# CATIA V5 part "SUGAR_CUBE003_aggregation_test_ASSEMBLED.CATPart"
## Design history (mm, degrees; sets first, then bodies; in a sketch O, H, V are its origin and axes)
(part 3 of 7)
Body19 "sugar_cube003_Ac004"
  Line128: type PtDir, RefPoint Point8, Direction edge [XY plane of AxisSystem1 | ZX plane of AxisSystem1], Start 0, End 3048 {= Body19.X1}
  Line129: type PtDir, RefPoint Point8, Direction edge [XY plane of AxisSystem1 | ZX plane of AxisSystem1], Start 0, End 5486.4 {= Body19.X2}
  Line130: type PtDir, RefPoint Point8, Direction edge [YZ plane of AxisSystem1 | XY plane of AxisSystem1], Start 0, End 3352.8 {= Body19.Y1}
  Line131: type PtDir, RefPoint Point8, Direction edge [YZ plane of AxisSystem1 | XY plane of AxisSystem1], Start 0, End 4572 {= Body19.Y2}
  Line132: type PtDir, RefPoint Point8, Direction edge [ZX plane of AxisSystem1 | YZ plane of AxisSystem1], Start 0, End 4876.8 {= Body19.Z1}
  Line133: type PtDir, RefPoint Point8, Direction edge [ZX plane of AxisSystem1 | YZ plane of AxisSystem1], Start 0, End 4572 {= Body19.Z2}
  Plane232: type Normal, Curve Line128, RefPoint vertex of Line128
  Plane233: type Normal, Curve Line129, RefPoint vertex of Line129
  Plane234: type Normal, Curve Line130, RefPoint vertex of Line130
  Plane235: type Normal, Curve Line131, RefPoint vertex of Line131
  Plane236: type Normal, Curve Line132, RefPoint vertex of Line132
  Plane237: type Normal, Curve Line133, RefPoint vertex of Line133
  Plane238: type 3Points, Element1 Point8, Element2 vertex of Line130, Element3 vertex of Line128
  Intersect341: ToIntersect1 Plane234, ToIntersect2 Plane233
  Intersect342: ToIntersect1 Plane232, ToIntersect2 Plane234
  Intersect343: ToIntersect1 Plane232, ToIntersect2 Plane235
  Intersect344: ToIntersect1 Plane235, ToIntersect2 Plane233
  MultiSel18
  LineCorner18: Elements ({intersect ToIntersect1 Plane238, ToIntersect2 Intersect343}; {intersect ToIntersect1 Plane238, ToIntersect2 Intersect344}; {intersect ToIntersect1 Plane238, ToIntersect2 Intersect341}; {intersect ToIntersect1 Plane238, ToIntersect2 Intersect342})
  Pad70: profile LineCorner18, up to Plane236, opposite side up to Plane237
  Plane239: type Offset, RefPlane Plane235, Offset 609.6 {= thickness}
  Plane240: type Offset, RefPlane Plane234, Offset 609.6 {= thickness}, reversed
  Plane241: type Offset, RefPlane Plane232, Offset 609.6 {= thickness}, reversed
  Plane242: type Offset, RefPlane Plane233, Offset 609.6 {= thickness}
  Plane243: type Offset, RefPlane Plane237, Offset 609.6 {= thickness}
  Plane244: type Offset, RefPlane Plane236, Offset 609.6 {= thickness}, reversed
  Intersect345: ToIntersect1 Plane239, ToIntersect2 Plane232
  Intersect346: ToIntersect1 Plane240, ToIntersect2 Plane232
  Intersect347: ToIntersect1 Plane243, ToIntersect2 Plane232
  Intersect348: ToIntersect1 Plane244, ToIntersect2 Plane232
  Trim205: Trimmed (Intersect345; Intersect348)
  Trim206: Trimmed (Trim205; Intersect346)
  Trim207: Trimmed (Trim206; Intersect347)
  Pocket74: profile Trim207, up to Plane242, deactivated
  Pad71: profile LineCorner18, up to Plane236, opposite side up to Plane237, deactivated
  Intersect349: ToIntersect1 Plane240, ToIntersect2 Plane233
  Intersect350: ToIntersect1 Plane233, ToIntersect2 Plane239
  Intersect351: ToIntersect1 Plane243, ToIntersect2 Plane233
  Intersect352: ToIntersect1 Plane244, ToIntersect2 Plane233
  Trim208: Trimmed (Intersect352; Intersect349)
  Trim209: Trimmed (Trim208; Intersect351)
  Trim210: Trimmed (Trim209; Intersect350)
  Pocket75: profile Trim210, up to Plane241, deactivated
  Intersect353: ToIntersect1 Plane242, ToIntersect2 Plane235
  Intersect354: ToIntersect1 Plane243, ToIntersect2 Plane235
  Intersect355: ToIntersect1 Plane235, ToIntersect2 Plane241
  Intersect356: ToIntersect1 Plane244, ToIntersect2 Plane235
  Trim211: Trimmed (Intersect353; Intersect356)
  Trim212: Trimmed (Trim211; Intersect355)
  Trim213: Trimmed (Trim212; Intersect354)
  Pad72: profile LineCorner18, up to Plane236, opposite side up to Plane237, deactivated
  Pocket76: profile Trim213, up to Plane240, deactivated
  Intersect357: ToIntersect1 Plane241, ToIntersect2 Plane234
  Intersect358: ToIntersect1 Plane243, ToIntersect2 Plane234
  Intersect359: ToIntersect1 Plane242, ToIntersect2 Plane234
  Intersect360: ToIntersect1 Plane244, ToIntersect2 Plane234
  Trim214: Trimmed (Intersect357; Intersect360)
  Trim215: Trimmed (Trim214; Intersect359)
  Trim216: Trimmed (Trim215; Intersect358)
  Pad73: profile LineCorner18, up to Plane236, opposite side up to Plane237
  Pocket77: profile Trim216, up to Plane239
Body20 "sugar_cube003_Ad004"
  Line134: type PtDir, RefPoint Point4, Direction edge [XY plane of AxisSystem1 | ZX plane of AxisSystem1], Start 0, End 3048 {= Body20.X1}
  Line135: type PtDir, RefPoint Point4, Direction edge [XY plane of AxisSystem1 | ZX plane of AxisSystem1], Start 0, End 4876.8 {= Body20.X2}
  Line136: type PtDir, RefPoint Point4, Direction edge [YZ plane of AxisSystem1 | XY plane of AxisSystem1], Start 0, End 5791.2 {= Body20.Y1}
  Line137: type PtDir, RefPoint Point4, Direction edge [YZ plane of AxisSystem1 | XY plane of AxisSystem1], Start 0, End 3048 {= Body20.Y2}
  Line138: type PtDir, RefPoint Point4, Direction edge [ZX plane of AxisSystem1 | YZ plane of AxisSystem1], Start 0, End 4876.8 {= Body20.Z1}
  Line139: type PtDir, RefPoint Point4, Direction edge [ZX plane of AxisSystem1 | YZ plane of AxisSystem1], Start 0, End 3962.4 {= Body20.Z2}
  Plane245: type Normal, Curve Line134, RefPoint vertex of Line134
  Plane246: type Normal, Curve Line135, RefPoint vertex of Line135
  Plane247: type Normal, Curve Line136, RefPoint vertex of Line136
  Plane248: type Normal, Curve Line137, RefPoint vertex of Line137
  Plane249: type Normal, Curve Line138, RefPoint vertex of Line138
  Plane250: type Normal, Curve Line139, RefPoint vertex of Line139
  Plane251: type 3Points, Element1 Point4, Element2 vertex of Line136, Element3 vertex of Line134
  Intersect361: ToIntersect1 Plane247, ToIntersect2 Plane246
  Intersect362: ToIntersect1 Plane245, ToIntersect2 Plane247
  Intersect363: ToIntersect1 Plane245, ToIntersect2 Plane248
  Intersect364: ToIntersect1 Plane248, ToIntersect2 Plane246
  MultiSel19
  LineCorner19: Elements ({intersect ToIntersect1 Plane251, ToIntersect2 Intersect363}; {intersect ToIntersect1 Plane251, ToIntersect2 Intersect364}; {intersect ToIntersect1 Plane251, ToIntersect2 Intersect361}; {intersect ToIntersect1 Plane251, ToIntersect2 Intersect362})
  Pad74: profile LineCorner19, up to Plane249, opposite side up to Plane250, deactivated
  Plane252: type Offset, RefPlane Plane248, Offset 609.6 {= thickness}
  Plane253: type Offset, RefPlane Plane247, Offset 609.6 {= thickness}, reversed
  Plane254: type Offset, RefPlane Plane245, Offset 609.6 {= thickness}, reversed
  Plane255: type Offset, RefPlane Plane246, Offset 609.6 {= thickness}
  Plane256: type Offset, RefPlane Plane250, Offset 609.6 {= thickness}
  Plane257: type Offset, RefPlane Plane249, Offset 609.6 {= thickness}, reversed
  Intersect365: ToIntersect1 Plane252, ToIntersect2 Plane245
  Intersect366: ToIntersect1 Plane253, ToIntersect2 Plane245
  Intersect367: ToIntersect1 Plane256, ToIntersect2 Plane245
  Intersect368: ToIntersect1 Plane257, ToIntersect2 Plane245
  Trim217: Trimmed (Intersect365; Intersect368)
  Trim218: Trimmed (Trim217; Intersect366)
  Trim219: Trimmed (Trim218; Intersect367)
  Pocket78: profile Trim219, up to Plane255, deactivated
  Pad75: profile LineCorner19, up to Plane249, opposite side up to Plane250, deactivated
  Intersect369: ToIntersect1 Plane253, ToIntersect2 Plane246
  Intersect370: ToIntersect1 Plane246, ToIntersect2 Plane252
  Intersect371: ToIntersect1 Plane256, ToIntersect2 Plane246
  Intersect372: ToIntersect1 Plane257, ToIntersect2 Plane246
  Trim220: Trimmed (Intersect372; Intersect369)
  Trim221: Trimmed (Trim220; Intersect371)
  Trim222: Trimmed (Trim221; Intersect370)
  Pocket79: profile Trim222, up to Plane254, deactivated
  Intersect373: ToIntersect1 Plane255, ToIntersect2 Plane248
  Intersect374: ToIntersect1 Plane256, ToIntersect2 Plane248
  Intersect375: ToIntersect1 Plane248, ToIntersect2 Plane254
  Intersect376: ToIntersect1 Plane257, ToIntersect2 Plane248
  Trim223: Trimmed (Intersect373; Intersect376)
  Trim224: Trimmed (Trim223; Intersect375)
  Trim225: Trimmed (Trim224; Intersect374)
  Pad76: profile LineCorner19, up to Plane249, opposite side up to Plane250
  Pocket80: profile Trim225, up to Plane253
  Intersect377: ToIntersect1 Plane254, ToIntersect2 Plane247
  Intersect378: ToIntersect1 Plane256, ToIntersect2 Plane247
  Intersect379: ToIntersect1 Plane255, ToIntersect2 Plane247
  Intersect380: ToIntersect1 Plane257, ToIntersect2 Plane247
  Trim226: Trimmed (Intersect377; Intersect380)
  Trim227: Trimmed (Trim226; Intersect379)
  Trim228: Trimmed (Trim227; Intersect378)
  Pad77: profile LineCorner19, up to Plane249, opposite side up to Plane250, deactivated
  Pocket81: profile Trim228, up to Plane252, deactivated
Body21 "sugar_cube003_Ae004"
  Line140: type PtDir, RefPoint Point100, Direction edge [XY plane of AxisSystem1 | ZX plane of AxisSystem1], Start 0, End 6096 {= Body21.X1}
  Line141: type PtDir, RefPoint Point100, Direction edge [XY plane of AxisSystem1 | ZX plane of AxisSystem1], Start 0, End 3352.8 {= Body21.X2}
  Line142: type PtDir, RefPoint Point100, Direction edge [YZ plane of AxisSystem1 | XY plane of AxisSystem1], Start 0, End 3657.6 {= Body21.Y1}
  Line143: type PtDir, RefPoint Point100, Direction edge [YZ plane of AxisSystem1 | XY plane of AxisSystem1], Start 0, End 5181.6 {= Body21.Y2}
  Line144: type PtDir, RefPoint Point100, Direction edge [ZX plane of AxisSystem1 | YZ plane of AxisSystem1], Start 0, End 5791.2 {= Body21.Z1}
  Line145: type PtDir, RefPoint Point100, Direction edge [ZX plane of AxisSystem1 | YZ plane of AxisSystem1], Start 0, End 3962.4 {= Body21.Z2}
  Plane258: type Normal, Curve Line140, RefPoint vertex of Line140
  Plane259: type Normal, Curve Line141, RefPoint vertex of Line141
  Plane260: type Normal, Curve Line142, RefPoint vertex of Line142
  Plane261: type Normal, Curve Line143, RefPoint vertex of Line143
  Plane262: type Normal, Curve Line144, RefPoint vertex of Line144
  Plane263: type Normal, Curve Line145, RefPoint vertex of Line145
  Plane264: type 3Points, Element1 Point100, Element2 vertex of Line142, Element3 vertex of Line140
  Intersect381: ToIntersect1 Plane260, ToIntersect2 Plane259
  Intersect382: ToIntersect1 Plane258, ToIntersect2 Plane260
  Intersect383: ToIntersect1 Plane258, ToIntersect2 Plane261
  Intersect384: ToIntersect1 Plane261, ToIntersect2 Plane259
  MultiSel20
  LineCorner20: Elements ({intersect ToIntersect1 Plane264, ToIntersect2 Intersect383}; {intersect ToIntersect1 Plane264, ToIntersect2 Intersect384}; {intersect ToIntersect1 Plane264, ToIntersect2 Intersect381}; {intersect ToIntersect1 Plane264, ToIntersect2 Intersect382})
  Pad78: profile LineCorner20, up to Plane262, opposite side up to Plane263, deactivated
  Plane265: type Offset, RefPlane Plane261, Offset 609.6 {= thickness}
  Plane266: type Offset, RefPlane Plane260, Offset 609.6 {= thickness}, reversed
  Plane267: type Offset, RefPlane Plane258, Offset 609.6 {= thickness}, reversed
  Plane268: type Offset, RefPlane Plane259, Offset 609.6 {= thickness}
  Plane269: type Offset, RefPlane Plane263, Offset 609.6 {= thickness}
  Plane270: type Offset, RefPlane Plane262, Offset 609.6 {= thickness}, reversed
  Intersect385: ToIntersect1 Plane265, ToIntersect2 Plane258
  Intersect386: ToIntersect1 Plane266, ToIntersect2 Plane258
  Intersect387: ToIntersect1 Plane269, ToIntersect2 Plane258
  Intersect388: ToIntersect1 Plane270, ToIntersect2 Plane258
  Trim229: Trimmed (Intersect385; Intersect388)
  Trim230: Trimmed (Trim229; Intersect386)
  Trim231: Trimmed (Trim230; Intersect387)
  Pocket82: profile Trim231, up to Plane268, deactivated
  Pad79: profile LineCorner20, up to Plane262, opposite side up to Plane263, deactivated
  Intersect389: ToIntersect1 Plane266, ToIntersect2 Plane259
  Intersect390: ToIntersect1 Plane259, ToIntersect2 Plane265
  Intersect391: ToIntersect1 Plane269, ToIntersect2 Plane259
  Intersect392: ToIntersect1 Plane270, ToIntersect2 Plane259
  Trim232: Trimmed (Intersect392; Intersect389)
  Trim233: Trimmed (Trim232; Intersect391)
  Trim234: Trimmed (Trim233; Intersect390)
  Pocket83: profile Trim234, up to Plane267, deactivated
  Intersect393: ToIntersect1 Plane268, ToIntersect2 Plane261
  Intersect394: ToIntersect1 Plane269, ToIntersect2 Plane261
  Intersect395: ToIntersect1 Plane261, ToIntersect2 Plane267
  Intersect396: ToIntersect1 Plane270, ToIntersect2 Plane261
  Trim235: Trimmed (Intersect393; Intersect396)
  Trim236: Trimmed (Trim235; Intersect395)
  Trim237: Trimmed (Trim236; Intersect394)
  Pad80: profile LineCorner20, up to Plane262, opposite side up to Plane263, deactivated
  Pocket84: profile Trim237, up to Plane266, deactivated
  Intersect397: ToIntersect1 Plane267, ToIntersect2 Plane260
  Intersect398: ToIntersect1 Plane269, ToIntersect2 Plane260
  Intersect399: ToIntersect1 Plane268, ToIntersect2 Plane260
  Intersect400: ToIntersect1 Plane270, ToIntersect2 Plane260
  Trim238: Trimmed (Intersect397; Intersect400)
  Trim239: Trimmed (Trim238; Intersect399)
  Trim240: Trimmed (Trim239; Intersect398)
  Pad81: profile LineCorner20, up to Plane262, opposite side up to Plane263, deactivated
  Pocket85: profile Trim240, up to Plane265, deactivated
Body22 "sugar_cube003_Aa005"
  Line146: type PtDir, RefPoint Point17, Direction edge [XY plane of AxisSystem1 | ZX plane of AxisSystem1], Start 0, End 3352.8 {= Body22.X1}
  Line147: type PtDir, RefPoint Point17, Direction edge [XY plane of AxisSystem1 | ZX plane of AxisSystem1], Start 0, End 3048 {= Body22.X2}
  Line148: type PtDir, RefPoint Point17, Direction edge [YZ plane of AxisSystem1 | XY plane of AxisSystem1], Start 0, End 3962.4 {= Body22.Y1}
  Line149: type PtDir, RefPoint Point17, Direction edge [YZ plane of AxisSystem1 | XY plane of AxisSystem1], Start 0, End 4572 {= Body22.Y2}
  Line150: type PtDir, RefPoint Point17, Direction edge [ZX plane of AxisSystem1 | YZ plane of AxisSystem1], Start 0, End 3352.8 {= Body22.Z1}
  Line151: type PtDir, RefPoint Point17, Direction edge [ZX plane of AxisSystem1 | YZ plane of AxisSystem1], Start 0, End 5791.2 {= Body22.Z2}
  Plane271: type Normal, Curve Line146, RefPoint vertex of Line146
  Plane272: type Normal, Curve Line147, RefPoint vertex of Line147
  Plane273: type Normal, Curve Line148, RefPoint vertex of Line148
  Plane274: type Normal, Curve Line149, RefPoint vertex of Line149
  Plane275: type Normal, Curve Line150, RefPoint vertex of Line150
  Plane276: type Normal, Curve Line151, RefPoint vertex of Line151
  Plane277: type 3Points, Element1 Point17, Element2 vertex of Line148, Element3 vertex of Line146
  Intersect401: ToIntersect1 Plane273, ToIntersect2 Plane272
  Intersect402: ToIntersect1 Plane271, ToIntersect2 Plane273
  Intersect403: ToIntersect1 Plane271, ToIntersect2 Plane274
  Intersect404: ToIntersect1 Plane274, ToIntersect2 Plane272
  MultiSel21
  LineCorner21: Elements ({intersect ToIntersect1 Plane277, ToIntersect2 Intersect403}; {intersect ToIntersect1 Plane277, ToIntersect2 Intersect404}; {intersect ToIntersect1 Plane277, ToIntersect2 Intersect401}; {intersect ToIntersect1 Plane277, ToIntersect2 Intersect402})
  Pad82: profile LineCorner21, up to Plane275, opposite side up to Plane276, deactivated
  Plane278: type Offset, RefPlane Plane274, Offset 609.6 {= thickness}
  Plane279: type Offset, RefPlane Plane273, Offset 609.6 {= thickness}, reversed
  Plane280: type Offset, RefPlane Plane271, Offset 609.6 {= thickness}, reversed
  Plane281: type Offset, RefPlane Plane272, Offset 609.6 {= thickness}
  Plane282: type Offset, RefPlane Plane276, Offset 609.6 {= thickness}
  Plane283: type Offset, RefPlane Plane275, Offset 609.6 {= thickness}, reversed
  Intersect405: ToIntersect1 Plane278, ToIntersect2 Plane271
  Intersect406: ToIntersect1 Plane279, ToIntersect2 Plane271
  Intersect407: ToIntersect1 Plane282, ToIntersect2 Plane271
  Intersect408: ToIntersect1 Plane283, ToIntersect2 Plane271
  Trim241: Trimmed (Intersect405; Intersect408)
  Trim242: Trimmed (Trim241; Intersect406)
  Trim243: Trimmed (Trim242; Intersect407)
  Pocket86: profile Trim243, up to Plane281, deactivated
  Pad83: profile LineCorner21, up to Plane275, opposite side up to Plane276, deactivated
  Intersect409: ToIntersect1 Plane279, ToIntersect2 Plane272
  Intersect410: ToIntersect1 Plane272, ToIntersect2 Plane278
  Intersect411: ToIntersect1 Plane282, ToIntersect2 Plane272
  Intersect412: ToIntersect1 Plane283, ToIntersect2 Plane272
  Trim244: Trimmed (Intersect412; Intersect409)
  Trim245: Trimmed (Trim244; Intersect411)
  Trim246: Trimmed (Trim245; Intersect410)
  Pocket87: profile Trim246, up to Plane280, deactivated
  Intersect413: ToIntersect1 Plane281, ToIntersect2 Plane274
  Intersect414: ToIntersect1 Plane282, ToIntersect2 Plane274
  Intersect415: ToIntersect1 Plane274, ToIntersect2 Plane280
  Intersect416: ToIntersect1 Plane283, ToIntersect2 Plane274
  Trim247: Trimmed (Intersect413; Intersect416)
  Trim248: Trimmed (Trim247; Intersect415)
  Trim249: Trimmed (Trim248; Intersect414)
  Pad84: profile LineCorner21, up to Plane275, opposite side up to Plane276, deactivated
  Pocket88: profile Trim249, up to Plane279, deactivated
  Intersect417: ToIntersect1 Plane280, ToIntersect2 Plane273
  Intersect418: ToIntersect1 Plane282, ToIntersect2 Plane273
  Intersect419: ToIntersect1 Plane281, ToIntersect2 Plane273
  Intersect420: ToIntersect1 Plane283, ToIntersect2 Plane273
  Trim250: Trimmed (Intersect417; Intersect420)
  Trim251: Trimmed (Trim250; Intersect419)
  Trim252: Trimmed (Trim251; Intersect418)
  Pad85: profile LineCorner21, up to Plane275, opposite side up to Plane276, deactivated
  Pocket89: profile Trim252, up to Plane278, deactivated
Body23 "sugar_cube003_Ab005"
  Line152: type PtDir, RefPoint Point13, Direction edge [XY plane of AxisSystem1 | ZX plane of AxisSystem1], Start 0, End 4572 {= Body23.X1}
  Line153: type PtDir, RefPoint Point13, Direction edge [XY plane of AxisSystem1 | ZX plane of AxisSystem1], Start 0, End 5486.4 {= Body23.X2}
  Line154: type PtDir, RefPoint Point13, Direction edge [YZ plane of AxisSystem1 | XY plane of AxisSystem1], Start 0, End 3657.6 {= Body23.Y1}
  Line155: type PtDir, RefPoint Point13, Direction edge [YZ plane of AxisSystem1 | XY plane of AxisSystem1], Start 0, End 5791.2 {= Body23.Y2}
  Line156: type PtDir, RefPoint Point13, Direction edge [ZX plane of AxisSystem1 | YZ plane of AxisSystem1], Start 0, End 3657.6 {= Body23.Z1}
  Line157: type PtDir, RefPoint Point13, Direction edge [ZX plane of AxisSystem1 | YZ plane of AxisSystem1], Start 0, End 5181.6 {= Body23.Z2}
  Plane284: type Normal, Curve Line152, RefPoint vertex of Line152
  Plane285: type Normal, Curve Line153, RefPoint vertex of Line153
  Plane286: type Normal, Curve Line154, RefPoint vertex of Line154
  Plane287: type Normal, Curve Line155, RefPoint vertex of Line155
  Plane288: type Normal, Curve Line156, RefPoint vertex of Line156
  Plane289: type Normal, Curve Line157, RefPoint vertex of Line157
  Plane290: type 3Points, Element1 Point13, Element2 vertex of Line154, Element3 vertex of Line152
  Intersect421: ToIntersect1 Plane286, ToIntersect2 Plane285
  Intersect422: ToIntersect1 Plane284, ToIntersect2 Plane286
  Intersect423: ToIntersect1 Plane284, ToIntersect2 Plane287
  Intersect424: ToIntersect1 Plane287, ToIntersect2 Plane285
  MultiSel22
  LineCorner22: Elements ({intersect ToIntersect1 Plane290, ToIntersect2 Intersect423}; {intersect ToIntersect1 Plane290, ToIntersect2 Intersect424}; {intersect ToIntersect1 Plane290, ToIntersect2 Intersect421}; {intersect ToIntersect1 Plane290, ToIntersect2 Intersect422})
  Pad86: profile LineCorner22, up to Plane288, opposite side up to Plane289
  Plane291: type Offset, RefPlane Plane287, Offset 609.6 {= thickness}
  Plane292: type Offset, RefPlane Plane286, Offset 609.6 {= thickness}, reversed
  Plane293: type Offset, RefPlane Plane284, Offset 609.6 {= thickness}, reversed
  Plane294: type Offset, RefPlane Plane285, Offset 609.6 {= thickness}
  Plane295: type Offset, RefPlane Plane289, Offset 609.6 {= thickness}
  Plane296: type Offset, RefPlane Plane288, Offset 609.6 {= thickness}, reversed
  Intersect425: ToIntersect1 Plane291, ToIntersect2 Plane284
  Intersect426: ToIntersect1 Plane292, ToIntersect2 Plane284
  Intersect427: ToIntersect1 Plane295, ToIntersect2 Plane284
  Intersect428: ToIntersect1 Plane296, ToIntersect2 Plane284
  Trim253: Trimmed (Intersect425; Intersect428)
  Trim254: Trimmed (Trim253; Intersect426)
  Trim255: Trimmed (Trim254; Intersect427)
  Pocket90: profile Trim255, up to Plane294, deactivated
  Pad87: profile LineCorner22, up to Plane288, opposite side up to Plane289, deactivated
  Intersect429: ToIntersect1 Plane292, ToIntersect2 Plane285
  Intersect430: ToIntersect1 Plane285, ToIntersect2 Plane291
  Intersect431: ToIntersect1 Plane295, ToIntersect2 Plane285
  Intersect432: ToIntersect1 Plane296, ToIntersect2 Plane285
  Trim256: Trimmed (Intersect432; Intersect429)
  Trim257: Trimmed (Trim256; Intersect431)
  Trim258: Trimmed (Trim257; Intersect430)
  Pocket91: profile Trim258, up to Plane293, deactivated
  Intersect433: ToIntersect1 Plane294, ToIntersect2 Plane287
  Intersect434: ToIntersect1 Plane295, ToIntersect2 Plane287
  Intersect435: ToIntersect1 Plane287, ToIntersect2 Plane293
  Intersect436: ToIntersect1 Plane296, ToIntersect2 Plane287
  Trim259: Trimmed (Intersect433; Intersect436)
  Trim260: Trimmed (Trim259; Intersect435)
  Trim261: Trimmed (Trim260; Intersect434)
  Pad88: profile LineCorner22, up to Plane288, opposite side up to Plane289, deactivated
  Pocket92: profile Trim261, up to Plane292, deactivated
  Intersect437: ToIntersect1 Plane293, ToIntersect2 Plane286
  Intersect438: ToIntersect1 Plane295, ToIntersect2 Plane286
  Intersect439: ToIntersect1 Plane294, ToIntersect2 Plane286
  Intersect440: ToIntersect1 Plane296, ToIntersect2 Plane286
  Trim262: Trimmed (Intersect437; Intersect440)
  Trim263: Trimmed (Trim262; Intersect439)
  Trim264: Trimmed (Trim263; Intersect438)
  Pad89: profile LineCorner22, up to Plane288, opposite side up to Plane289, deactivated
  Pocket93: profile Trim264, up to Plane291, deactivated
Body24 "sugar_cube003_Ac005"
  Line158: type PtDir, RefPoint Point9, Direction edge [XY plane of AxisSystem1 | ZX plane of AxisSystem1], Start 0, End 3962.4 {= Body24.X1}
  Line159: type PtDir, RefPoint Point9, Direction edge [XY plane of AxisSystem1 | ZX plane of AxisSystem1], Start 0, End 4876.8 {= Body24.X2}
  Line160: type PtDir, RefPoint Point9, Direction edge [YZ plane of AxisSystem1 | XY plane of AxisSystem1], Start 0, End 4876.8 {= Body24.Y1}
  Line161: type PtDir, RefPoint Point9, Direction edge [YZ plane of AxisSystem1 | XY plane of AxisSystem1], Start 0, End 4267.2 {= Body24.Y2}
  Line162: type PtDir, RefPoint Point9, Direction edge [ZX plane of AxisSystem1 | YZ plane of AxisSystem1], Start 0, End 3048 {= Body24.Z1}
  Line163: type PtDir, RefPoint Point9, Direction edge [ZX plane of AxisSystem1 | YZ plane of AxisSystem1], Start 0, End 3048 {= Body24.Z2}
  Plane297: type Normal, Curve Line158, RefPoint vertex of Line158
  Plane298: type Normal, Curve Line159, RefPoint vertex of Line159
  Plane299: type Normal, Curve Line160, RefPoint vertex of Line160
  Plane300: type Normal, Curve Line161, RefPoint vertex of Line161
  Plane301: type Normal, Curve Line162, RefPoint vertex of Line162
  Plane302: type Normal, Curve Line163, RefPoint vertex of Line163
  Plane303: type 3Points, Element1 Point9, Element2 vertex of Line160, Element3 vertex of Line158
  Intersect441: ToIntersect1 Plane299, ToIntersect2 Plane298
  Intersect442: ToIntersect1 Plane297, ToIntersect2 Plane299
  Intersect443: ToIntersect1 Plane297, ToIntersect2 Plane300
  Intersect444: ToIntersect1 Plane300, ToIntersect2 Plane298
  MultiSel23
  LineCorner23: Elements ({intersect ToIntersect1 Plane303, ToIntersect2 Intersect443}; {intersect ToIntersect1 Plane303, ToIntersect2 Intersect444}; {intersect ToIntersect1 Plane303, ToIntersect2 Intersect441}; {intersect ToIntersect1 Plane303, ToIntersect2 Intersect442})
  Pad90: profile LineCorner23, up to Plane301, opposite side up to Plane302
  Plane304: type Offset, RefPlane Plane300, Offset 609.6 {= thickness}
  Plane305: type Offset, RefPlane Plane299, Offset 609.6 {= thickness}, reversed
  Plane306: type Offset, RefPlane Plane297, Offset 609.6 {= thickness}, reversed
  Plane307: type Offset, RefPlane Plane298, Offset 609.6 {= thickness}
  Plane308: type Offset, RefPlane Plane302, Offset 609.6 {= thickness}
  Plane309: type Offset, RefPlane Plane301, Offset 609.6 {= thickness}, reversed
  Intersect445: ToIntersect1 Plane304, ToIntersect2 Plane297
  Intersect446: ToIntersect1 Plane305, ToIntersect2 Plane297
  Intersect447: ToIntersect1 Plane308, ToIntersect2 Plane297
  Intersect448: ToIntersect1 Plane309, ToIntersect2 Plane297
  Trim265: Trimmed (Intersect445; Intersect448)
  Trim266: Trimmed (Trim265; Intersect446)
  Trim267: Trimmed (Trim266; Intersect447)
  Pocket94: profile Trim267, up to Plane307, deactivated
  Pad91: profile LineCorner23, up to Plane301, opposite side up to Plane302, deactivated
  Intersect449: ToIntersect1 Plane305, ToIntersect2 Plane298
  Intersect450: ToIntersect1 Plane298, ToIntersect2 Plane304
  Intersect451: ToIntersect1 Plane308, ToIntersect2 Plane298
  Intersect452: ToIntersect1 Plane309, ToIntersect2 Plane298
  Trim268: Trimmed (Intersect452; Intersect449)
  Trim269: Trimmed (Trim268; Intersect451)
  Trim270: Trimmed (Trim269; Intersect450)
  Pocket95: profile Trim270, up to Plane306, deactivated
  Intersect453: ToIntersect1 Plane307, ToIntersect2 Plane300
  Intersect454: ToIntersect1 Plane308, ToIntersect2 Plane300
  Intersect455: ToIntersect1 Plane300, ToIntersect2 Plane306
  Intersect456: ToIntersect1 Plane309, ToIntersect2 Plane300
  Trim271: Trimmed (Intersect453; Intersect456)
  Trim272: Trimmed (Trim271; Intersect455)
  Trim273: Trimmed (Trim272; Intersect454)
  Pad92: profile LineCorner23, up to Plane301, opposite side up to Plane302, deactivated
  Pocket96: profile Trim273, up to Plane305, deactivated
  Intersect457: ToIntersect1 Plane306, ToIntersect2 Plane299
  Intersect458: ToIntersect1 Plane308, ToIntersect2 Plane299
  Intersect459: ToIntersect1 Plane307, ToIntersect2 Plane299
  Intersect460: ToIntersect1 Plane309, ToIntersect2 Plane299
  Trim274: Trimmed (Intersect457; Intersect460)
  Trim275: Trimmed (Trim274; Intersect459)
  Trim276: Trimmed (Trim275; Intersect458)
  Pad93: profile LineCorner23, up to Plane301, opposite side up to Plane302
  Pocket97: profile Trim276, up to Plane304
Body25 "sugar_cube003_Ad005"
  Line164: type PtDir, RefPoint Point5, Direction edge [XY plane of AxisSystem1 | ZX plane of AxisSystem1], Start 0, End 6096 {= Body25.X1}
  Line165: type PtDir, RefPoint Point5, Direction edge [XY plane of AxisSystem1 | ZX plane of AxisSystem1], Start 0, End 5486.4 {= Body25.X2}
  Line166: type PtDir, RefPoint Point5, Direction edge [YZ plane of AxisSystem1 | XY plane of AxisSystem1], Start 0, End 3048 {= Body25.Y1}
  Line167: type PtDir, RefPoint Point5, Direction edge [YZ plane of AxisSystem1 | XY plane of AxisSystem1], Start 0, End 5486.4 {= Body25.Y2}
  Line168: type PtDir, RefPoint Point5, Direction edge [ZX plane of AxisSystem1 | YZ plane of AxisSystem1], Start 0, End 5181.6 {= Body25.Z1}
  Line169: type PtDir, RefPoint Point5, Direction edge [ZX plane of AxisSystem1 | YZ plane of AxisSystem1], Start 0, End 5486.4 {= Body25.Z2}
  Plane310: type Normal, Curve Line164, RefPoint vertex of Line164
  Plane311: type Normal, Curve Line165, RefPoint vertex of Line165
  Plane312: type Normal, Curve Line166, RefPoint vertex of Line166
  Plane313: type Normal, Curve Line167, RefPoint vertex of Line167
  Plane314: type Normal, Curve Line168, RefPoint vertex of Line168
  Plane315: type Normal, Curve Line169, RefPoint vertex of Line169
  Plane316: type 3Points, Element1 Point5, Element2 vertex of Line166, Element3 vertex of Line164
  Intersect461: ToIntersect1 Plane312, ToIntersect2 Plane311
  Intersect462: ToIntersect1 Plane310, ToIntersect2 Plane312
  Intersect463: ToIntersect1 Plane310, ToIntersect2 Plane313
  Intersect464: ToIntersect1 Plane313, ToIntersect2 Plane311
  MultiSel24
  LineCorner24: Elements ({intersect ToIntersect1 Plane316, ToIntersect2 Intersect463}; {intersect ToIntersect1 Plane316, ToIntersect2 Intersect464}; {intersect ToIntersect1 Plane316, ToIntersect2 Intersect461}; {intersect ToIntersect1 Plane316, ToIntersect2 Intersect462})
  Pad94: profile LineCorner24, up to Plane314, opposite side up to Plane315, deactivated
  Plane317: type Offset, RefPlane Plane313, Offset 609.6 {= thickness}
  Plane318: type Offset, RefPlane Plane312, Offset 609.6 {= thickness}, reversed
  Plane319: type Offset, RefPlane Plane310, Offset 609.6 {= thickness}, reversed
  Plane320: type Offset, RefPlane Plane311, Offset 609.6 {= thickness}
  Plane321: type Offset, RefPlane Plane315, Offset 609.6 {= thickness}
  Plane322: type Offset, RefPlane Plane314, Offset 609.6 {= thickness}, reversed
  Intersect465: ToIntersect1 Plane317, ToIntersect2 Plane310
  Intersect466: ToIntersect1 Plane318, ToIntersect2 Plane310
  Intersect467: ToIntersect1 Plane321, ToIntersect2 Plane310
  Intersect468: ToIntersect1 Plane322, ToIntersect2 Plane310
  Trim277: Trimmed (Intersect465; Intersect468)
  Trim278: Trimmed (Trim277; Intersect466)
  Trim279: Trimmed (Trim278; Intersect467)
  Pocket98: profile Trim279, up to Plane320, deactivated
  Pad95: profile LineCorner24, up to Plane314, opposite side up to Plane315, deactivated
  Intersect469: ToIntersect1 Plane318, ToIntersect2 Plane311
  Intersect470: ToIntersect1 Plane311, ToIntersect2 Plane317
  Intersect471: ToIntersect1 Plane321, ToIntersect2 Plane311
  Intersect472: ToIntersect1 Plane322, ToIntersect2 Plane311
  Trim280: Trimmed (Intersect472; Intersect469)
  Trim281: Trimmed (Trim280; Intersect471)
  Trim282: Trimmed (Trim281; Intersect470)
  Pocket99: profile Trim282, up to Plane319, deactivated
  Intersect473: ToIntersect1 Plane320, ToIntersect2 Plane313
  Intersect474: ToIntersect1 Plane321, ToIntersect2 Plane313
  Intersect475: ToIntersect1 Plane313, ToIntersect2 Plane319
  Intersect476: ToIntersect1 Plane322, ToIntersect2 Plane313
  Trim283: Trimmed (Intersect473; Intersect476)
  Trim284: Trimmed (Trim283; Intersect475)
  Trim285: Trimmed (Trim284; Intersect474)
  Pad96: profile LineCorner24, up to Plane314, opposite side up to Plane315, deactivated
  Pocket100: profile Trim285, up to Plane318, deactivated
  Intersect477: ToIntersect1 Plane319, ToIntersect2 Plane312
  Intersect478: ToIntersect1 Plane321, ToIntersect2 Plane312
  Intersect479: ToIntersect1 Plane320, ToIntersect2 Plane312
  Intersect480: ToIntersect1 Plane322, ToIntersect2 Plane312
  Trim286: Trimmed (Intersect477; Intersect480)
  Trim287: Trimmed (Trim286; Intersect479)
  Trim288: Trimmed (Trim287; Intersect478)
  Pad97: profile LineCorner24, up to Plane314, opposite side up to Plane315, deactivated
  Pocket101: profile Trim288, up to Plane317, deactivated
Body26 "sugar_cube003Ae005"
  Line170: type PtDir, RefPoint Point101, Direction edge [XY plane of AxisSystem1 | ZX plane of AxisSystem1], Start 0, End 3352.8 {= Body26.X1}
  Line171: type PtDir, RefPoint Point101, Direction edge [XY plane of AxisSystem1 | ZX plane of AxisSystem1], Start 0, End 3962.4 {= Body26.X2}
  Line172: type PtDir, RefPoint Point101, Direction edge [YZ plane of AxisSystem1 | XY plane of AxisSystem1], Start 0, End 5791.2 {= Body26.Y1}
  Line173: type PtDir, RefPoint Point101, Direction edge [YZ plane of AxisSystem1 | XY plane of AxisSystem1], Start 0, End 4572 {= Body26.Y2}
  Line174: type PtDir, RefPoint Point101, Direction edge [ZX plane of AxisSystem1 | YZ plane of AxisSystem1], Start 0, End 4267.2 {= Body26.Z1}
  Line175: type PtDir, RefPoint Point101, Direction edge [ZX plane of AxisSystem1 | YZ plane of AxisSystem1], Start 0, End 4267.2 {= Body26.Z2}
  Plane323: type Normal, Curve Line170, RefPoint vertex of Line170
  Plane324: type Normal, Curve Line171, RefPoint vertex of Line171
  Plane325: type Normal, Curve Line172, RefPoint vertex of Line172
  Plane326: type Normal, Curve Line173, RefPoint vertex of Line173
  Plane327: type Normal, Curve Line174, RefPoint vertex of Line174
  Plane328: type Normal, Curve Line175, RefPoint vertex of Line175
  Plane329: type 3Points, Element1 Point101, Element2 vertex of Line172, Element3 vertex of Line170
  Intersect481: ToIntersect1 Plane325, ToIntersect2 Plane324
  Intersect482: ToIntersect1 Plane323, ToIntersect2 Plane325
  Intersect483: ToIntersect1 Plane323, ToIntersect2 Plane326
  Intersect484: ToIntersect1 Plane326, ToIntersect2 Plane324
  MultiSel25
  LineCorner25: Elements ({intersect ToIntersect1 Plane329, ToIntersect2 Intersect483}; {intersect ToIntersect1 Plane329, ToIntersect2 Intersect484}; {intersect ToIntersect1 Plane329, ToIntersect2 Intersect481}; {intersect ToIntersect1 Plane329, ToIntersect2 Intersect482})
  Pad98: profile LineCorner25, up to Plane327, opposite side up to Plane328
  Plane330: type Offset, RefPlane Plane326, Offset 609.6 {= thickness}
  Plane331: type Offset, RefPlane Plane325, Offset 609.6 {= thickness}, reversed
  Plane332: type Offset, RefPlane Plane323, Offset 609.6 {= thickness}, reversed
  Plane333: type Offset, RefPlane Plane324, Offset 609.6 {= thickness}
  Plane334: type Offset, RefPlane Plane328, Offset 609.6 {= thickness}
  Plane335: type Offset, RefPlane Plane327, Offset 609.6 {= thickness}, reversed
  Intersect485: ToIntersect1 Plane330, ToIntersect2 Plane323
  Intersect486: ToIntersect1 Plane331, ToIntersect2 Plane323
  Intersect487: ToIntersect1 Plane334, ToIntersect2 Plane323
  Intersect488: ToIntersect1 Plane335, ToIntersect2 Plane323
  Trim289: Trimmed (Intersect485; Intersect488)
  Trim290: Trimmed (Trim289; Intersect486)
  Trim291: Trimmed (Trim290; Intersect487)
  Pocket102: profile Trim291, up to Plane333, deactivated
  Pad99: profile LineCorner25, up to Plane327, opposite side up to Plane328, deactivated
  Intersect489: ToIntersect1 Plane331, ToIntersect2 Plane324
  Intersect490: ToIntersect1 Plane324, ToIntersect2 Plane330
  Intersect491: ToIntersect1 Plane334, ToIntersect2 Plane324
  Intersect492: ToIntersect1 Plane335, ToIntersect2 Plane324
  Trim292: Trimmed (Intersect492; Intersect489)
  Trim293: Trimmed (Trim292; Intersect491)
  Trim294: Trimmed (Trim293; Intersect490)
  Pocket103: profile Trim294, up to Plane332, deactivated
  Intersect493: ToIntersect1 Plane333, ToIntersect2 Plane326
  Intersect494: ToIntersect1 Plane334, ToIntersect2 Plane326
  Intersect495: ToIntersect1 Plane326, ToIntersect2 Plane332
  Intersect496: ToIntersect1 Plane335, ToIntersect2 Plane326
  Trim295: Trimmed (Intersect493; Intersect496)
  Trim296: Trimmed (Trim295; Intersect495)
  Trim297: Trimmed (Trim296; Intersect494)
  Pad100: profile LineCorner25, up to Plane327, opposite side up to Plane328, deactivated
  Pocket104: profile Trim297, up to Plane331, deactivated
  Intersect497: ToIntersect1 Plane332, ToIntersect2 Plane325
  Intersect498: ToIntersect1 Plane334, ToIntersect2 Plane325
  Intersect499: ToIntersect1 Plane333, ToIntersect2 Plane325
  Intersect500: ToIntersect1 Plane335, ToIntersect2 Plane325
  Trim298: Trimmed (Intersect497; Intersect500)
  Trim299: Trimmed (Trim298; Intersect499)
  Trim300: Trimmed (Trim299; Intersect498)
  Pad101: profile LineCorner25, up to Plane327, opposite side up to Plane328, deactivated
  Pocket105: profile Trim300, up to Plane330, deactivated
Body27 "sugar_cube003_Ba002"
  Line176: type PtDir, RefPoint Point34, Direction edge [XY plane of AxisSystem1 | ZX plane of AxisSystem1], Start 0, End 4267.2 {= Body27.X1}
  Line177: type PtDir, RefPoint Point34, Direction edge [XY plane of AxisSystem1 | ZX plane of AxisSystem1], Start 0, End 3657.6 {= Body27.X2}
  Line178: type PtDir, RefPoint Point34, Direction edge [YZ plane of AxisSystem1 | XY plane of AxisSystem1], Start 0, End 3657.6 {= Body27.Y1}
  Line179: type PtDir, RefPoint Point34, Direction edge [YZ plane of AxisSystem1 | XY plane of AxisSystem1], Start 0, End 3657.6 {= Body27.Y2}
  Line180: type PtDir, RefPoint Point34, Direction edge [ZX plane of AxisSystem1 | YZ plane of AxisSystem1], Start 0, End 5181.6 {= Body27.Z1}
  Line181: type PtDir, RefPoint Point34, Direction edge [ZX plane of AxisSystem1 | YZ plane of AxisSystem1], Start 0, End 6096 {= Body27.Z2}
  Plane336: type Normal, Curve Line176, RefPoint vertex of Line176
  Plane337: type Normal, Curve Line177, RefPoint vertex of Line177
  Plane338: type Normal, Curve Line178, RefPoint vertex of Line178
  Plane339: type Normal, Curve Line179, RefPoint vertex of Line179
  Plane340: type Normal, Curve Line180, RefPoint vertex of Line180
  Plane341: type Normal, Curve Line181, RefPoint vertex of Line181
  Plane342: type 3Points, Element1 Point34, Element2 vertex of Line178, Element3 vertex of Line176
  Intersect501: ToIntersect1 Plane338, ToIntersect2 Plane337
  Intersect502: ToIntersect1 Plane336, ToIntersect2 Plane338
  Intersect503: ToIntersect1 Plane336, ToIntersect2 Plane339
  Intersect504: ToIntersect1 Plane339, ToIntersect2 Plane337
  MultiSel26
  LineCorner26: Elements ({intersect ToIntersect1 Plane342, ToIntersect2 Intersect503}; {intersect ToIntersect1 Plane342, ToIntersect2 Intersect504}; {intersect ToIntersect1 Plane342, ToIntersect2 Intersect501}; {intersect ToIntersect1 Plane342, ToIntersect2 Intersect502})
  Pad102: profile LineCorner26, up to Plane340, opposite side up to Plane341
  Plane343: type Offset, RefPlane Plane339, Offset 609.6 {= thickness}
  Plane344: type Offset, RefPlane Plane338, Offset 609.6 {= thickness}, reversed
  Plane345: type Offset, RefPlane Plane336, Offset 609.6 {= thickness}, reversed
  Plane346: type Offset, RefPlane Plane337, Offset 609.6 {= thickness}
  Plane347: type Offset, RefPlane Plane341, Offset 609.6 {= thickness}
  Plane348: type Offset, RefPlane Plane340, Offset 609.6 {= thickness}, reversed
  Intersect505: ToIntersect1 Plane343, ToIntersect2 Plane336
  Intersect506: ToIntersect1 Plane344, ToIntersect2 Plane336
  Intersect507: ToIntersect1 Plane347, ToIntersect2 Plane336
  Intersect508: ToIntersect1 Plane348, ToIntersect2 Plane336
  Trim301: Trimmed (Intersect505; Intersect508)
  Trim302: Trimmed (Trim301; Intersect506)
  Trim303: Trimmed (Trim302; Intersect507)
  Pocket106: profile Trim303, up to Plane346
  Pad103: profile LineCorner26, up to Plane340, opposite side up to Plane341, deactivated
  Intersect509: ToIntersect1 Plane344, ToIntersect2 Plane337
  Intersect510: ToIntersect1 Plane337, ToIntersect2 Plane343
  Intersect511: ToIntersect1 Plane347, ToIntersect2 Plane337
  Intersect512: ToIntersect1 Plane348, ToIntersect2 Plane337
  Trim304: Trimmed (Intersect512; Intersect509)
  Trim305: Trimmed (Trim304; Intersect511)
  Trim306: Trimmed (Trim305; Intersect510)
  Pocket107: profile Trim306, up to Plane345, deactivated
  Intersect513: ToIntersect1 Plane346, ToIntersect2 Plane339
  Intersect514: ToIntersect1 Plane347, ToIntersect2 Plane339
  Intersect515: ToIntersect1 Plane339, ToIntersect2 Plane345
  Intersect516: ToIntersect1 Plane348, ToIntersect2 Plane339
  Trim307: Trimmed (Intersect513; Intersect516)
  Trim308: Trimmed (Trim307; Intersect515)
  Trim309: Trimmed (Trim308; Intersect514)
  Pad104: profile LineCorner26, up to Plane340, opposite side up to Plane341, deactivated
  Pocket108: profile Trim309, up to Plane344, deactivated
  Intersect517: ToIntersect1 Plane345, ToIntersect2 Plane338
  Intersect518: ToIntersect1 Plane347, ToIntersect2 Plane338
  Intersect519: ToIntersect1 Plane346, ToIntersect2 Plane338
  Intersect520: ToIntersect1 Plane348, ToIntersect2 Plane338
  Trim310: Trimmed (Intersect517; Intersect520)
  Trim311: Trimmed (Trim310; Intersect519)
  Trim312: Trimmed (Trim311; Intersect518)
  Pad105: profile LineCorner26, up to Plane340, opposite side up to Plane341, deactivated
  Pocket109: profile Trim312, up to Plane343, deactivated
Body28 "sugar_cube003_Bb002"
  Line182: type PtDir, RefPoint Point30, Direction edge [XY plane of AxisSystem1 | ZX plane of AxisSystem1], Start 0, End 5791.2 {= Body28.X1}
  Line183: type PtDir, RefPoint Point30, Direction edge [XY plane of AxisSystem1 | ZX plane of AxisSystem1], Start 0, End 3352.8 {= Body28.X2}
  Line184: type PtDir, RefPoint Point30, Direction edge [YZ plane of AxisSystem1 | XY plane of AxisSystem1], Start 0, End 4876.8 {= Body28.Y1}
  Line185: type PtDir, RefPoint Point30, Direction edge [YZ plane of AxisSystem1 | XY plane of AxisSystem1], Start 0, End 4572 {= Body28.Y2}
  Line186: type PtDir, RefPoint Point30, Direction edge [ZX plane of AxisSystem1 | YZ plane of AxisSystem1], Start 0, End 3352.8 {= Body28.Z1}
  Line187: type PtDir, RefPoint Point30, Direction edge [ZX plane of AxisSystem1 | YZ plane of AxisSystem1], Start 0, End 4876.8 {= Body28.Z2}
  Plane349: type Normal, Curve Line182, RefPoint vertex of Line182
  Plane350: type Normal, Curve Line183, RefPoint vertex of Line183
  Plane351: type Normal, Curve Line184, RefPoint vertex of Line184
  Plane352: type Normal, Curve Line185, RefPoint vertex of Line185
  Plane353: type Normal, Curve Line186, RefPoint vertex of Line186
  Plane354: type Normal, Curve Line187, RefPoint vertex of Line187
  Plane355: type 3Points, Element1 Point30, Element2 vertex of Line184, Element3 vertex of Line182
  Intersect521: ToIntersect1 Plane351, ToIntersect2 Plane350
  Intersect522: ToIntersect1 Plane349, ToIntersect2 Plane351
  Intersect523: ToIntersect1 Plane349, ToIntersect2 Plane352
  Intersect524: ToIntersect1 Plane352, ToIntersect2 Plane350
  MultiSel27
  LineCorner27: Elements ({intersect ToIntersect1 Plane355, ToIntersect2 Intersect523}; {intersect ToIntersect1 Plane355, ToIntersect2 Intersect524}; {intersect ToIntersect1 Plane355, ToIntersect2 Intersect521}; {intersect ToIntersect1 Plane355, ToIntersect2 Intersect522})
  Pad106: profile LineCorner27, up to Plane353, opposite side up to Plane354, deactivated
  Plane356: type Offset, RefPlane Plane352, Offset 609.6 {= thickness}
  Plane357: type Offset, RefPlane Plane351, Offset 609.6 {= thickness}, reversed
  Plane358: type Offset, RefPlane Plane349, Offset 609.6 {= thickness}, reversed
  Plane359: type Offset, RefPlane Plane350, Offset 609.6 {= thickness}
  Plane360: type Offset, RefPlane Plane354, Offset 609.6 {= thickness}
  Plane361: type Offset, RefPlane Plane353, Offset 609.6 {= thickness}, reversed
  Intersect525: ToIntersect1 Plane356, ToIntersect2 Plane349
  Intersect526: ToIntersect1 Plane357, ToIntersect2 Plane349
  Intersect527: ToIntersect1 Plane360, ToIntersect2 Plane349
  Intersect528: ToIntersect1 Plane361, ToIntersect2 Plane349
  Trim313: Trimmed (Intersect525; Intersect528)
  Trim314: Trimmed (Trim313; Intersect526)
  Trim315: Trimmed (Trim314; Intersect527)
  Pocket110: profile Trim315, up to Plane359, deactivated
  Pad107: profile LineCorner27, up to Plane353, opposite side up to Plane354, deactivated
  Intersect529: ToIntersect1 Plane357, ToIntersect2 Plane350
  Intersect530: ToIntersect1 Plane350, ToIntersect2 Plane356
  Intersect531: ToIntersect1 Plane360, ToIntersect2 Plane350
  Intersect532: ToIntersect1 Plane361, ToIntersect2 Plane350
  Trim316: Trimmed (Intersect532; Intersect529)
  Trim317: Trimmed (Trim316; Intersect531)
  Trim318: Trimmed (Trim317; Intersect530)
  Pocket111: profile Trim318, up to Plane358, deactivated
  Intersect533: ToIntersect1 Plane359, ToIntersect2 Plane352
  Intersect534: ToIntersect1 Plane360, ToIntersect2 Plane352
  Intersect535: ToIntersect1 Plane352, ToIntersect2 Plane358
  Intersect536: ToIntersect1 Plane361, ToIntersect2 Plane352
  Trim319: Trimmed (Intersect533; Intersect536)
  Trim320: Trimmed (Trim319; Intersect535)
  Trim321: Trimmed (Trim320; Intersect534)
  Pad108: profile LineCorner27, up to Plane353, opposite side up to Plane354, deactivated
  Pocket112: profile Trim321, up to Plane357, deactivated
  Intersect537: ToIntersect1 Plane358, ToIntersect2 Plane351
  Intersect538: ToIntersect1 Plane360, ToIntersect2 Plane351
  Intersect539: ToIntersect1 Plane359, ToIntersect2 Plane351
  Intersect540: ToIntersect1 Plane361, ToIntersect2 Plane351
  Trim322: Trimmed (Intersect537; Intersect540)
  Trim323: Trimmed (Trim322; Intersect539)
  Trim324: Trimmed (Trim323; Intersect538)
  Pad109: profile LineCorner27, up to Plane353, opposite side up to Plane354
  Pocket113: profile Trim324, up to Plane356
Body29 "sugar_cube003_Bc002"
  Line188: type PtDir, RefPoint Point26, Direction edge [XY plane of AxisSystem1 | ZX plane of AxisSystem1], Start 0, End 3962.4 {= Body29.X1}
  Line189: type PtDir, RefPoint Point26, Direction edge [XY plane of AxisSystem1 | ZX plane of AxisSystem1], Start 0, End 4267.2 {= Body29.X2}
  Line190: type PtDir, RefPoint Point26, Direction edge [YZ plane of AxisSystem1 | XY plane of AxisSystem1], Start 0, End 5791.2 {= Body29.Y1}
  Line191: type PtDir, RefPoint Point26, Direction edge [YZ plane of AxisSystem1 | XY plane of AxisSystem1], Start 0, End 3352.8 {= Body29.Y2}
  Line192: type PtDir, RefPoint Point26, Direction edge [ZX plane of AxisSystem1 | YZ plane of AxisSystem1], Start 0, End 6096 {= Body29.Z1}
  Line193: type PtDir, RefPoint Point26, Direction edge [ZX plane of AxisSystem1 | YZ plane of AxisSystem1], Start 0, End 4876.8 {= Body29.Z2}
  Plane362: type Normal, Curve Line188, RefPoint vertex of Line188
  Plane363: type Normal, Curve Line189, RefPoint vertex of Line189
  Plane364: type Normal, Curve Line190, RefPoint vertex of Line190
  Plane365: type Normal, Curve Line191, RefPoint vertex of Line191
  Plane366: type Normal, Curve Line192, RefPoint vertex of Line192
  Plane367: type Normal, Curve Line193, RefPoint vertex of Line193
  Plane368: type 3Points, Element1 Point26, Element2 vertex of Line190, Element3 vertex of Line188
  Intersect541: ToIntersect1 Plane364, ToIntersect2 Plane363
  Intersect542: ToIntersect1 Plane362, ToIntersect2 Plane364
  Intersect543: ToIntersect1 Plane362, ToIntersect2 Plane365
  Intersect544: ToIntersect1 Plane365, ToIntersect2 Plane363
  MultiSel28
  LineCorner28: Elements ({intersect ToIntersect1 Plane368, ToIntersect2 Intersect543}; {intersect ToIntersect1 Plane368, ToIntersect2 Intersect544}; {intersect ToIntersect1 Plane368, ToIntersect2 Intersect541}; {intersect ToIntersect1 Plane368, ToIntersect2 Intersect542})
  Pad110: profile LineCorner28, up to Plane366, opposite side up to Plane367
  Plane369: type Offset, RefPlane Plane365, Offset 609.6 {= thickness}
  Plane370: type Offset, RefPlane Plane364, Offset 609.6 {= thickness}, reversed
  Plane371: type Offset, RefPlane Plane362, Offset 609.6 {= thickness}, reversed
  Plane372: type Offset, RefPlane Plane363, Offset 609.6 {= thickness}
  Plane373: type Offset, RefPlane Plane367, Offset 609.6 {= thickness}
  Plane374: type Offset, RefPlane Plane366, Offset 609.6 {= thickness}, reversed
  Intersect545: ToIntersect1 Plane369, ToIntersect2 Plane362
  Intersect546: ToIntersect1 Plane370, ToIntersect2 Plane362
  Intersect547: ToIntersect1 Plane373, ToIntersect2 Plane362
  Intersect548: ToIntersect1 Plane374, ToIntersect2 Plane362
  Trim325: Trimmed (Intersect545; Intersect548)
  Trim326: Trimmed (Trim325; Intersect546)
  Trim327: Trimmed (Trim326; Intersect547)
  Pocket114: profile Trim327, up to Plane372, deactivated
  Pad111: profile LineCorner28, up to Plane366, opposite side up to Plane367, deactivated
  Intersect549: ToIntersect1 Plane370, ToIntersect2 Plane363
  Intersect550: ToIntersect1 Plane363, ToIntersect2 Plane369
  Intersect551: ToIntersect1 Plane373, ToIntersect2 Plane363
  Intersect552: ToIntersect1 Plane374, ToIntersect2 Plane363
  Trim328: Trimmed (Intersect552; Intersect549)
  Trim329: Trimmed (Trim328; Intersect551)
  Trim330: Trimmed (Trim329; Intersect550)
  Pocket115: profile Trim330, up to Plane371, deactivated
  Intersect553: ToIntersect1 Plane372, ToIntersect2 Plane365
  Intersect554: ToIntersect1 Plane373, ToIntersect2 Plane365
  Intersect555: ToIntersect1 Plane365, ToIntersect2 Plane371
  Intersect556: ToIntersect1 Plane374, ToIntersect2 Plane365
  Trim331: Trimmed (Intersect553; Intersect556)
  Trim332: Trimmed (Trim331; Intersect555)
  Trim333: Trimmed (Trim332; Intersect554)
  Pad112: profile LineCorner28, up to Plane366, opposite side up to Plane367, deactivated
  Pocket116: profile Trim333, up to Plane370, deactivated
  Intersect557: ToIntersect1 Plane371, ToIntersect2 Plane364
  Intersect558: ToIntersect1 Plane373, ToIntersect2 Plane364
  Intersect559: ToIntersect1 Plane372, ToIntersect2 Plane364
  Intersect560: ToIntersect1 Plane374, ToIntersect2 Plane364
  Trim334: Trimmed (Intersect557; Intersect560)
  Trim335: Trimmed (Trim334; Intersect559)
  Trim336: Trimmed (Trim335; Intersect558)
  Pad113: profile LineCorner28, up to Plane366, opposite side up to Plane367, deactivated
  Pocket117: profile Trim336, up to Plane369, deactivated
